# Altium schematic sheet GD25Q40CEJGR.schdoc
size 127 x 101 mm
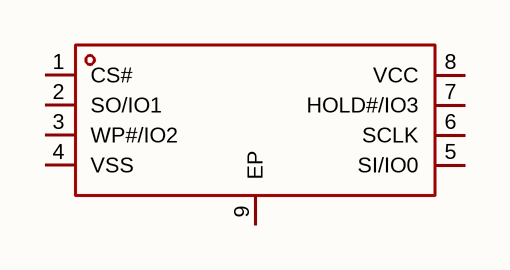
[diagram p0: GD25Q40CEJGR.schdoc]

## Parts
U?  gd25q40cejgr  [USON-8_L3.0-W2.0-P0.50-BL-EP_WINBOND_UX]  (value not drawn)

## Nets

Not connected (* = marked no-connect by the designer): U? 1(CS#) 2(SO/IO1) 3(WP#/IO2) 4(VSS) 5(SI/IO0) 6(SCLK) 7(HOLD#/IO3) 8(VCC) 9(EP)

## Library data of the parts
U? = gd25q40cejgr: 接口类型:SPI;存储容量:4Mbit;时钟频率(fc):120MHz;; Manufacturer: GigaDevice(兆易创新); AddInBom: yes; ModelId: 12a239e5c7384371915ecb51201bf581; ModelName: USON-8_L3.0-W2.0-H0.6-P0.50; ModelTransform: 118.8974,78.74,0,90,0,0,0,0,0; Interface: SPI; Memory Size: 4Mbit; Clock Frequency: 120MHz; Voltage - Supply: 2.7V~3.6V; Standby Supply Current: 1uA; Program / Erase Cycles: 100000次; Data Retention - TDR (Year): 20年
